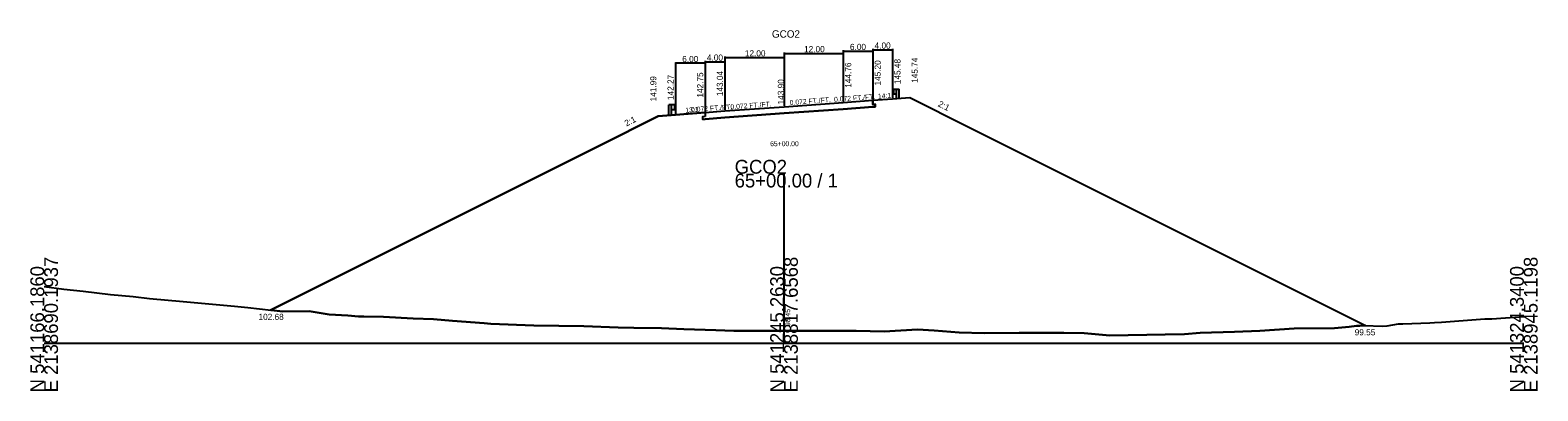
# Model space of a CAD drawing. Extents: x -14327 to 8886, y -10 to 39048.
# Drawn here: x 1997.2 to 2302.8, y 29990.3 to 30063.4 of the extents above; entities that cross this region are included whole.
import ezdxf

# ---------------------------------------------------------------- set-up
doc = ezdxf.new("R2010")
doc.units = 0
for name, color, linetype in [('Level 1', 7, 'Continuous'), ('Level 5', 7, 'Continuous'), ('Level 53', 7, 'Continuous'), ('Level 54', 7, 'Continuous'), ('Level 55', 7, 'Continuous'), ('Level 7', 7, 'Continuous'), ('RD_GPK_XS_Cell', 7, 'Continuous'), ('RD_XS_EwShp', 7, 'Continuous'), ('RD_XS_ExGround', 7, 'Continuous'), ('RD_XS_Pave', 7, 'Continuous'), ('RD_XS_TX_Baseline', 7, 'Continuous'), ('RD_XS_TX_Elev_EX', 7, 'Continuous'), ('RD_XS_TX_Elev_PR', 7, 'Continuous'), ('RD_XS_TX_Station', 7, 'Continuous')]:
    doc.layers.add(name, color=color, linetype=linetype)

msp = doc.modelspace()

# ---------------------------------------------------------------- linework, layer by layer
at = {"layer": 'Level 1'}
for p, q in [((2172.02, 30051.3), (2172.14, 30051.39)), ((2172.02, 30051.2), (2172.14, 30051.11)), ((2172.02, 30050.77), (2172.14, 30050.86)), ((2172.02, 30050.67), (2172.14, 30050.58)), ((2172.15, 30051.4), (2172.23, 30051.41)), ((2172.15, 30050.57), (2172.23, 30050.56)), ((2172.16, 30051.06), (2172.16, 30050.91)), ((2172.23, 30051.47), (2172.23, 30050.5)), ((2172.23, 30051.47), (2172.78, 30051.47)), ((2172.23, 30050.5), (2172.78, 30050.5)), ((2172.78, 30049.48), (2172.78, 30051.47)), ((2172.78, 30051.47), (2173.34, 30051.47)), ((2173.34, 30049.48), (2173.34, 30051.47)), ((2126.66, 30046.27), (2126.66, 30048.26)), ((2127.22, 30048.26), (2126.66, 30048.26)), ((2127.22, 30046.27), (2127.22, 30048.26)), ((2127.77, 30048.26), (2127.22, 30048.26)), ((2127.77, 30047.28), (2127.22, 30047.28)), ((2127.77, 30048.26), (2127.77, 30047.28)), ((2127.85, 30048.18), (2127.77, 30048.19)), ((2127.85, 30047.36), (2127.77, 30047.34)), ((2127.84, 30047.85), (2127.84, 30047.69)), ((2127.98, 30048.08), (2127.86, 30048.18)), ((2127.98, 30047.98), (2127.86, 30047.89)), ((2127.98, 30047.56), (2127.86, 30047.65)), ((2127.98, 30047.45), (2127.86, 30047.36))]:
    msp.add_line(p, q, dxfattribs=at)
for centre, radius, start, end in [((2172.07, 30051.25), 0.0651, 129.0336, 230.9663), ((2172.07, 30050.72), 0.0651, 129.0336, 230.9663), ((2172.09, 30050.91), 0.0651, 302.9895, 0), ((2172.15, 30051.37), 0.026, 90, 129.0505), ((2172.09, 30051.06), 0.0651, 0, 45), ((2172.15, 30050.6), 0.026, 230.9496, 270), ((2127.91, 30047.85), 0.0651, 135, 180), ((2127.91, 30047.69), 0.0651, 180, 237.0105), ((2127.85, 30048.16), 0.026, 50.9495, 90), ((2127.85, 30047.38), 0.026, 270, 309.0504), ((2127.93, 30048.03), 0.0651, 309.0337, 50.9664), ((2127.93, 30047.5), 0.0651, 309.0337, 50.9664)]:
    msp.add_arc(centre, radius, start, end, dxfattribs=at)
at = {"layer": 'Level 5'}
for p, q in [((2168, 30049.2), (2168, 30048.36)), ((2134, 30045.91), (2133.5, 30045.88)), ((2133.5, 30045.88), (2133.5, 30045.38)), ((2134, 30046.75), (2134, 30045.91)), ((2138, 30045.7), (2134, 30045.41)), ((2150, 30046.57), (2138, 30045.7)), ((2162, 30047.43), (2150, 30046.57)), ((2168, 30047.86), (2162, 30047.43)), ((2168, 30048.36), (2168.5, 30048.4)), ((2168.5, 30047.9), (2168, 30047.86)), ((2168.5, 30048.4), (2168.5, 30047.9)), ((2133.5, 30045.38), (2134, 30045.41))]:
    msp.add_line(p, q, dxfattribs=at)
at = {"layer": 'Level 54'}
for p, q in [((2138, 30058.05), (2138, 30047.24)), ((2138, 30057.85), (2150, 30057.85)), ((2150, 30058.91), (2150, 30048.1)), ((2150, 30058.71), (2162, 30058.71)), ((2150, 30058.05), (2150, 30048.1)), ((2162, 30059.35), (2162, 30048.96)), ((2162, 30059.15), (2168, 30059.15)), ((2162, 30058.91), (2162, 30048.96)), ((2168, 30059.63), (2168, 30049.4)), ((2168, 30059.43), (2172, 30059.43)), ((2168, 30059.35), (2168, 30049.4)), ((2172, 30059.63), (2172, 30049.68)), ((2128, 30056.9), (2128, 30046.47)), ((2134, 30056.7), (2128, 30056.7)), ((2134, 30057.19), (2134, 30046.95)), ((2134, 30056.99), (2138, 30056.99)), ((2134, 30056.9), (2134, 30046.95)), ((2138, 30057.19), (2138, 30047.24))]:
    msp.add_line(p, q, dxfattribs=at)
at = {"layer": 'Level 7'}
for p, q in [((2168, 30049.2), (2172, 30049.48)), ((2172, 30049.48), (2175.5, 30049.74)), ((2175.5, 30049.74), (2187.5, 30043.74)), ((2124.5, 30045.99), (2112.5, 30039.99)), ((2128, 30046.27), (2124.5, 30045.99)), ((2134, 30046.75), (2128, 30046.27)), ((2187.5, 30043.74), (2267.88, 30003.55)), ((2112.5, 30039.99), (2045.89, 30006.68))]:
    msp.add_line(p, q, dxfattribs=at)
at = {"layer": 'RD_GPK_XS_Cell'}
for p, q in [((2150, 30000), (2150, 30034.33)), ((2000, 30000), (2150, 30000)), ((2150, 30000), (2300, 30000))]:
    msp.add_line(p, q, dxfattribs=at)
at = {"layer": 'RD_XS_EwShp'}
msp.add_lwpolyline([(2134, 30045.91), (2133.5, 30045.88), (2133.5, 30045.38), (2134, 30045.41), (2138, 30045.7), (2150, 30046.57), (2162, 30047.43), (2168, 30047.86), (2168.5, 30047.9), (2168.5, 30048.4), (2168, 30048.36), (2168, 30049.2), (2172, 30049.48), (2175.5, 30049.74), (2187.5, 30043.74), (2267.88, 30003.55), (2267.62, 30003.55), (2266.78, 30003.47), (2266.05, 30003.46), (2264.6, 30003.25), (2261.61, 30003.03), (2253.44, 30002.95), (2246.5, 30002.46), (2241.32, 30002.27), (2234.4, 30002.05), (2231.17, 30001.8), (2227.26, 30001.72), (2216.04, 30001.5), (2210.87, 30001.97), (2206.76, 30002.09), (2197.7, 30002.05), (2190.58, 30001.99), (2185.5, 30002.16), (2180.43, 30002.55), (2177.07, 30002.71), (2170.28, 30002.36), (2164.6, 30002.44), (2160.13, 30002.45), (2154.8, 30002.45), (2150, 30002.45), (2142.39, 30002.45), (2139.84, 30002.49), (2136.18, 30002.64), (2129.69, 30002.84), (2125.16, 30002.99), (2119.54, 30003.09), (2116.35, 30003.16), (2109.39, 30003.4), (2099.29, 30003.58), (2090.59, 30003.87), (2089.21, 30004.04), (2082.82, 30004.48), (2078.95, 30004.81), (2074.83, 30004.99), (2068.8, 30005.32), (2064.84, 30005.39), (2063.71, 30005.39), (2061.6, 30005.55), (2057.77, 30005.81), (2053.72, 30006.48), (2048.42, 30006.41), (2045.89, 30006.68), (2112.5, 30039.99), (2124.5, 30045.99), (2128, 30046.27), (2134, 30046.75)], close=True, dxfattribs=at)
at = {"layer": 'RD_XS_ExGround'}
for p, q in [((2000, 30011.44), (2003.97, 30010.91)), ((2003.97, 30010.91), (2007.91, 30010.49)), ((2007.91, 30010.49), (2013.45, 30009.83)), ((2013.45, 30009.83), (2018.06, 30009.4)), ((2018.06, 30009.4), (2021.33, 30009.05)), ((2021.33, 30009.05), (2028.21, 30008.41)), ((2028.21, 30008.41), (2038.6, 30007.46)), ((2038.6, 30007.46), (2041.26, 30007.17)), ((2041.26, 30007.17), (2048.42, 30006.41)), ((2048.42, 30006.41), (2053.72, 30006.48)), ((2053.72, 30006.48), (2057.77, 30005.81)), ((2057.77, 30005.81), (2061.6, 30005.55)), ((2061.6, 30005.55), (2063.71, 30005.39)), ((2063.71, 30005.39), (2064.84, 30005.39)), ((2064.84, 30005.39), (2068.8, 30005.32)), ((2068.8, 30005.32), (2074.83, 30004.99)), ((2074.83, 30004.99), (2078.95, 30004.81)), ((2078.95, 30004.81), (2082.82, 30004.48)), ((2082.82, 30004.48), (2089.21, 30004.04)), ((2089.21, 30004.04), (2090.59, 30003.87)), ((2090.59, 30003.87), (2099.29, 30003.58)), ((2099.29, 30003.58), (2109.39, 30003.4)), ((2109.39, 30003.4), (2116.35, 30003.16)), ((2116.35, 30003.16), (2119.54, 30003.09)), ((2119.54, 30003.09), (2125.16, 30002.99)), ((2125.16, 30002.99), (2129.69, 30002.84)), ((2129.69, 30002.84), (2136.18, 30002.64)), ((2136.18, 30002.64), (2139.84, 30002.49)), ((2170.28, 30002.36), (2177.07, 30002.71)), ((2177.07, 30002.71), (2180.43, 30002.55)), ((2246.5, 30002.46), (2253.44, 30002.95)), ((2253.44, 30002.95), (2261.61, 30003.03)), ((2261.61, 30003.03), (2264.6, 30003.25)), ((2264.6, 30003.25), (2266.05, 30003.46)), ((2266.05, 30003.46), (2266.78, 30003.47)), ((2266.78, 30003.47), (2267.62, 30003.55)), ((2267.62, 30003.55), (2271.33, 30003.45)), ((2271.33, 30003.45), (2272.27, 30003.5)), ((2272.27, 30003.5), (2274.61, 30003.92)), ((2274.61, 30003.92), (2275.45, 30003.92)), ((2275.45, 30003.92), (2280.96, 30004.07)), ((2280.96, 30004.07), (2281.91, 30004.14)), ((2281.91, 30004.14), (2283.28, 30004.25)), ((2283.28, 30004.25), (2292.06, 30004.88)), ((2292.06, 30004.88), (2293.54, 30004.93)), ((2293.54, 30004.93), (2300, 30005.38)), ((2139.84, 30002.49), (2142.39, 30002.45)), ((2142.39, 30002.45), (2150, 30002.45)), ((2150, 30002.45), (2154.8, 30002.45)), ((2154.8, 30002.45), (2160.13, 30002.45)), ((2160.13, 30002.45), (2164.6, 30002.44)), ((2164.6, 30002.44), (2170.28, 30002.36)), ((2180.43, 30002.55), (2185.5, 30002.16)), ((2185.5, 30002.16), (2190.58, 30001.99)), ((2190.58, 30001.99), (2197.7, 30002.05)), ((2197.7, 30002.05), (2206.76, 30002.09)), ((2206.76, 30002.09), (2210.87, 30001.97)), ((2210.87, 30001.97), (2216.04, 30001.5)), ((2216.04, 30001.5), (2227.26, 30001.72)), ((2227.26, 30001.72), (2231.17, 30001.8)), ((2231.17, 30001.8), (2234.4, 30002.05)), ((2234.4, 30002.05), (2241.32, 30002.27)), ((2241.32, 30002.27), (2246.5, 30002.46))]:
    msp.add_line(p, q, dxfattribs=at)
at = {"layer": 'RD_XS_Pave'}
for p, q in [((2150, 30047.9), (2162, 30048.76)), ((2162, 30048.76), (2168, 30049.2)), ((2134, 30046.75), (2138, 30047.04)), ((2138, 30047.04), (2150, 30047.9))]:
    msp.add_line(p, q, dxfattribs=at)

# ---------------------------------------------------------------- texts
at = {"layer": 'Level 53'}
for s, rotation, p in [('145.74', 90, (2177.12, 30052.74)), ('142.75', 90, (2133.63, 30049.75)), ('143.04', 90, (2137.62, 30050.04)), ('144.76', 90, (2163.63, 30051.76)), ('145.20', 90, (2169.62, 30052.2)), ('145.48', 90, (2173.62, 30052.48)), ('141.99', 90, (2124.13, 30048.99)), ('142.27', 90, (2127.63, 30049.27)), ('2:1', 333.4349, (2181.11, 30048.05)), ('2:1', 26.5651, (2118.05, 30043.88))]:
    msp.add_text(s, height=1.25, rotation=rotation, dxfattribs=at).set_placement(p)
for s, p in [('102.68', (2043.46, 30004.68)), ('99.55', (2265.71, 30001.55))]:
    msp.add_text(s, height=1.25, dxfattribs=at).set_placement(p)
at = {"layer": 'Level 54'}
for s, p in [('4.00', (2168.37, 30059.68)), ('6.00', (2129.37, 30056.95)), ('4.00', (2134.37, 30057.24)), ('12.00', (2142.07, 30058.1)), ('12.00', (2154.07, 30058.96)), ('6.00', (2163.37, 30059.4))]:
    msp.add_text(s, height=1.25, dxfattribs=at).set_placement(p)
at = {"layer": 'Level 55'}
for s, rotation, p in [('0.072 FT./FT.', 4.1182, (2139.18, 30047.37)), ('0.072 FT./FT.', 4.1182, (2151.18, 30048.24)), ('0.072 FT./FT.', 4.1182, (2160.18, 30048.88)), ('14:1', 4.1182, (2169.08, 30049.52)), ('13:1', 4.5739, (2130.03, 30046.68)), ('0.072 FT./FT.', 4.1182, (2131.18, 30046.8))]:
    msp.add_text(s, height=1, rotation=rotation, dxfattribs=at).set_placement(p)
at = {"layer": 'RD_GPK_XS_Cell'}
for s, p in [('GCO2', (2140, 30034.33)), ('65+00.00 / 1', (2140, 30031.53))]:
    msp.add_text(s, height=2.8, dxfattribs=at).set_placement(p)
for s, p in [('N 541166.1860', (2000, 29990)), ('E 2138690.1937', (2002.8, 29990)), ('N 541245.2630', (2150, 29990)), ('E 2138817.6568', (2152.8, 29990)), ('N 541324.3400', (2300, 29990)), ('E 2138945.1198', (2302.8, 29990))]:
    msp.add_text(s, height=2.8, rotation=90, dxfattribs=at).set_placement(p)
at = {"layer": 'RD_XS_TX_Baseline'}
msp.add_text('GCO2', height=1.5, dxfattribs=at).set_placement((2147.55, 30061.9))
at = {"layer": 'RD_XS_TX_Elev_EX'}
msp.add_text('98.45', height=1, rotation=90, dxfattribs=at).set_placement((2151.25, 30003.45))
at = {"layer": 'RD_XS_TX_Elev_PR'}
msp.add_text(' 143.90', height=1.25, rotation=90, dxfattribs=at).set_placement((2150, 30047.9))
at = {"layer": 'RD_XS_TX_Station'}
msp.add_text('65+00.00', height=1, dxfattribs=at).set_placement((2147.19, 30039.9))

doc.saveas('drawing.dxf')
